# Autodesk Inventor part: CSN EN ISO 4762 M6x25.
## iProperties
Shininess: 20.0
Length Units: 11269
Angle Units: 11279
Time Units: 11290
Mass Units: 11283
Length Display Precision: 3
Angle Display Precision: 2
+MSCProtocol1+ProtocolID: P08052013571767102
+MSCProtocol2+Protocol: P08052013571767102<@PID>[Data]<@EL>P=1{mm<@EL>L=25{mm<@EL>d=6{mm<@EL>Dh=10{mm<@EL>k=6{mm<@EL>t=3{mm<@EL>s=5{mm<@EL>r1=0.25{mm<@EL>r2=0.6{mm<@EL>b=23{mm<@EL>mass
Created: 2001-01
Part Number: CSN EN ISO 4762 M6x25.
Material: Steel, Mild
Document SubType Name: Modeling
Description: Bolt M6x25 CSN EN ISO 4762.
Standard: CSN EN ISO 4762
Density: 7.86
Volumn: 2.805817155661937
Area: 16.25312931541364
PropertySet Name: Model Information
Control State: 0
Master: False
Checked Out: False
BOM1: Bolt
BOM2: M6x25
BOM3: CSN EN ISO 4762
Revision Number: 1
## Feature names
1. ExtrusionBlind1
2. Chamfer1
3. ExtrusionBlind2
4. ExtrusionBlind3
5. Fillet1
6. Fillet2
